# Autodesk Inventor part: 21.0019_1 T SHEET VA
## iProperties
Created: 2012-11
Part Number: 21.0019_1 T SHEET VA
Document SubType Name: Modeling
Designer: Administrator
Density: 8.08 g/cm^3
Material: Stainless Steel
Mass: 289.556 g
Surface Area: 173.051 cm^2
Volume: 35.8361 cm^3
Author: Administrator
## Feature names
1. Extrusion1
2. Extrusion2
3. Hole1
4. Fillet1
